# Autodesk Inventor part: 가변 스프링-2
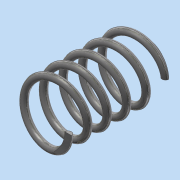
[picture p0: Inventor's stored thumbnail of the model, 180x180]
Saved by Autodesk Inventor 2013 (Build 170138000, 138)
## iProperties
Created: 2018-10
Part Number: 가변 스프링-2
Material: 스테인리스강
Document SubType Name: Modeling
Designer: Administrator
Density: 8.08 g/cm^3
Mass: 6.28229 g
Surface Area: 15.7857 cm^2
Volume: 0.777511 cm^3
Author: Administrator
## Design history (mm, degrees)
sketch "스케치1"
  geometry: L1 (0, 0)-(0, 24.507); L2 (0.539, 0)-(8, 0); L3 (0, 24.507)-(8, 24.507); C1 r 1 at (8, 0)
  constraints: 6 end point, 1 centre point, 1 horizontal alignment, 1 parallel, 1 perpendicular, 1 vertical
  dimensions: "d0" = 24.50699 distance of L1.start L1.end (derived); "d1" = 2 diameter of C1; "d2" = 16 diameter of L2.end L1; "d3" = 8 distance of L1.end L3.end
feature "코일1" sketch "스케치1" pitch "d4" = 10; turns "d6" = 5; dims "d5" = 24.50699 (= d0), "d7" = 0, angle "d8" = 90 deg, angle "d9" = 90 deg, "d10" = 0, "d11" = 0
sketch "스케치2"
  geometry: L1 (24.507, 11)-(0, 11); L2 (0, 11)-(0, -11); L3 (0, -11)-(24.507, -11); L4 (24.507, -11)-(24.507, 11); 2 further points
  constraints: 8 end point, 2 parallel, 1 coincident, 1 horizontal, 1 midpoint, 1 perpendicular
  dimensions: "d12" = 24.50699 distance of L3.end L2.end (derived); "d13" = 22 distance of L2.end L1.end
extrude "돌출1" sketch "스케치2" stored distance "d14" = 0; taper "d15" = 0 deg
node "솔리드1"
